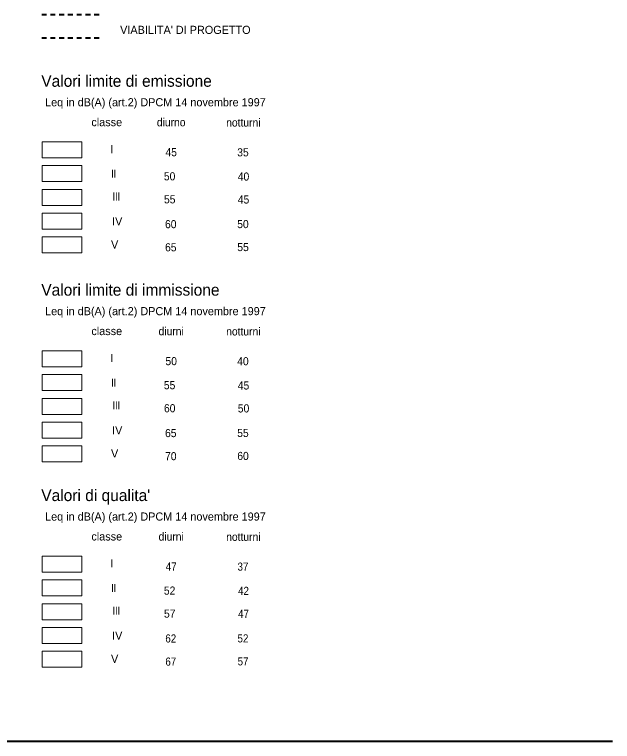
# Model space of a CAD drawing. Extents: x 652791 to 656927, y 889884 to 892405.
# Drawn here: x 653862 to 654894, y 889884 to 891138 of the extents above; entities that cross this region are included whole.
import ezdxf
from ezdxf.enums import TextEntityAlignment as Align

# ---------------------------------------------------------------- set-up
doc = ezdxf.new("R2010")
doc.units = 0
doc.header["$LTSCALE"] = 5.6
doc.linetypes.add('SHORT_DASHED', pattern=[2.7, 1.5, -1.2])
doc.layers.add('61', color=7, linetype='Continuous', lineweight=35)

msp = doc.modelspace()

# ---------------------------------------------------------------- linework, layer by layer
at = {"layer": '61', "linetype": 'SHORT_DASHED', "lineweight": 40}
for p, q in [((653908.93, 891138.02), (654008.61, 891138.02)), ((653908.93, 891098.02), (654008.61, 891098.02))]:
    msp.add_line(p, q, dxfattribs=at)
at = {"layer": '61', "lineweight": 40}
msp.add_line((654894.04, 889884.41), (652791.02, 889884.41), dxfattribs=at)
at = {"layer": '61', "lineweight": 13}
for points in [[(653909.6, 890918.42), (653978.14, 890918.42), (653978.14, 890890.7), (653909.6, 890890.7)], [(653909.6, 890877.72), (653978.14, 890877.72), (653978.14, 890850), (653909.6, 890850)], [(653909.6, 890836.14), (653978.14, 890836.14), (653978.14, 890808.42), (653909.6, 890808.42)], [(653909.6, 890795.42), (653978.14, 890795.42), (653978.14, 890767.7), (653909.6, 890767.7)], [(653909.6, 890754.7), (653978.14, 890754.7), (653978.14, 890726.98), (653909.6, 890726.98)], [(653909.6, 890558.16), (653978.14, 890558.16), (653978.14, 890530.44), (653909.6, 890530.44)], [(653909.6, 890517.46), (653978.14, 890517.46), (653978.14, 890489.74), (653909.6, 890489.74)], [(653909.6, 890475.88), (653978.14, 890475.88), (653978.14, 890448.16), (653909.6, 890448.16)], [(653909.6, 890435.16), (653978.14, 890435.16), (653978.14, 890407.44), (653909.6, 890407.44)], [(653909.6, 890394.44), (653978.14, 890394.44), (653978.14, 890366.72), (653909.6, 890366.72)], [(653909.6, 890203.95), (653978.14, 890203.95), (653978.14, 890176.23), (653909.6, 890176.23)], [(653909.6, 890163.25), (653978.14, 890163.25), (653978.14, 890135.53), (653909.6, 890135.53)], [(653909.6, 890121.67), (653978.14, 890121.67), (653978.14, 890093.95), (653909.6, 890093.95)], [(653909.6, 890080.95), (653978.14, 890080.95), (653978.14, 890053.23), (653909.6, 890053.23)], [(653909.6, 890040.23), (653978.14, 890040.23), (653978.14, 890012.51), (653909.6, 890012.51)]]:
    msp.add_lwpolyline(points, close=True, dxfattribs=at)

# ---------------------------------------------------------------- texts
at = {"layer": '61'}
for s, height, p in [("VIABILITA' DI PROGETTO", 14, (654044.32, 891104.61)), ('Valori limite di emissione', 20, (653908.23, 891013.45)), ('Leq in dB(A) (art.2) DPCM 14 novembre 1997', 14, (653914.81, 890979.77)), ('Valori limite di immissione', 20, (653908.23, 890653.19)), ('Leq in dB(A) (art.2) DPCM 14 novembre 1997', 14, (653914.81, 890619.51)), ("Valori di qualita'", 20, (653908.23, 890298.97)), ('Leq in dB(A) (art.2) DPCM 14 novembre 1997', 14, (653914.81, 890265.29))]:
    msp.add_text(s, height=height, dxfattribs=at).set_placement(p)
for s, p in [('classe', (654021.22, 890945.45)), ('I', (654030.24, 890898.92)), ('IV', (654039.32, 890774.36)), ('V', (654034.83, 890734.42)), ('classe', (654021.22, 890585.19)), ('I', (654030.24, 890538.66)), ('IV', (654039.32, 890414.1)), ('V', (654034.83, 890374.16)), ('classe', (654021.22, 890230.97)), ('I', (654030.24, 890184.44)), ('IV', (654039.32, 890059.88)), ('V', (654034.83, 890019.94))]:
    msp.add_text(s, height=14, dxfattribs=at).set_placement(p, align=Align.CENTER)
for s, width, p in [('diurno', 0.95, (654132.44, 890945.25)), ('notturni', 0.95, (654257, 890944.81)), ('45', 0.95, (654132.44, 890893.59)), ('35', 0.95, (654256.29, 890893.41)), ('II', 0.8, (654033.18, 890856.6)), (' 50', 0.95, (654127.23, 890852.05)), ('40', 0.95, (654257.27, 890851.61)), ('III', 0.85, (654037.79, 890817.3)), (' 55', 0.95, (654127.41, 890812.33)), ('45', 0.95, (654257.31, 890812.07)), ('60', 0.95, (654131.69, 890769.53)), ('50', 0.95, (654256.27, 890769.67)), ('65', 0.95, (654131.74, 890729.63)), ('55', 0.95, (654256.44, 890730.05)), ('diurni', 0.95, (654132.44, 890584.99)), ('notturni', 0.95, (654257, 890584.55)), ('50', 0.95, (654132.44, 890533.33)), ('40', 0.95, (654256.29, 890533.15)), ('II', 0.8, (654033.18, 890496.34)), (' 55', 0.95, (654127.23, 890491.79)), ('45', 0.95, (654257.27, 890491.35)), ('III', 0.85, (654037.79, 890457.04)), (' 60', 0.95, (654127.41, 890452.07)), ('50', 0.95, (654257.31, 890451.81)), ('65', 0.95, (654131.69, 890409.27)), ('55', 0.95, (654256.27, 890409.41)), ('70', 0.95, (654131.74, 890369.37)), ('60', 0.95, (654256.44, 890369.79)), ('diurni', 0.95, (654132.44, 890230.77)), ('notturni', 0.95, (654257, 890230.33)), ('47', 0.9, (654132.44, 890179.11)), ('37', 0.9, (654256.28, 890178.93)), ('II', 0.8, (654033.18, 890142.12)), (' 52', 0.95, (654127.23, 890137.57)), ('42', 0.9, (654257.26, 890137.13)), ('III', 0.85, (654037.79, 890102.82)), (' 57', 0.95, (654127.42, 890097.85)), ('47', 0.9, (654257.3, 890097.59)), ('62', 0.9, (654131.68, 890055.05)), ('52', 0.9, (654256.26, 890055.19)), ('67', 0.9, (654131.74, 890015.15)), ('57', 0.9, (654256.44, 890015.57))]:
    msp.add_text(s, height=14, dxfattribs=dict(at, width=width)).set_placement(p, align=Align.CENTER)

doc.saveas('drawing.dxf')
